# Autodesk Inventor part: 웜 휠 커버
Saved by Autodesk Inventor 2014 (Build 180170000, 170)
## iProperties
Created: 2025-06
Part Number: 웜 휠 커버
Material: 일반
Document SubType Name: Modeling
Designer: dg
Density: 1 g/cm^3
Appearance: 기본값
Author: dg
Author: jhkim
Creation Date: 2025-05-23
Sending System: Autodesk Inventor 2026
Preprocessor: ST-DEVELOPER v20.1
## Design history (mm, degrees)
node "웜 휠 커버1"
node "솔리드1"
node "기준1"
